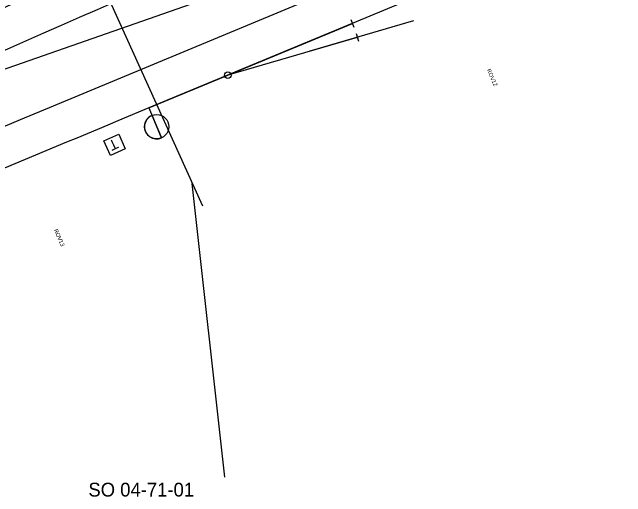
# Model space of a CAD drawing. Extents: x -723225 to -722352, y -1040354 to -1039760.
# Drawn here: x -723166.4 to -723090.8, y -1040339.7 to -1040280 of the extents above; entities that cross this region are included whole.
import ezdxf

# ---------------------------------------------------------------- set-up
doc = ezdxf.new("R2010")
doc.units = 0
for name, color, linetype in [('_PS_SO_číslo', 7, 'Continuous'), ('PS 05_01_01', 7, 'Continuous'), ('PS 05_02_22', 7, 'Continuous'), ('SO 03_01_01', 7, 'Continuous'), ('SO_04_71_01', 7, 'Continuous')]:
    doc.layers.add(name, color=color, linetype=linetype)

msp = doc.modelspace()

# ---------------------------------------------------------------- linework, layer by layer
at = {"layer": '_PS_SO_číslo'}
msp.add_line((-723140.168, -1040337.306), (-723144.203, -1040301.118), dxfattribs=at)
at = {"layer": 'PS 05_01_01'}
msp.add_lwpolyline([(-723219.2, -1040319.871), (-723217.435, -1040319.27), (-723221.975, -1040306.095), (-723205.95, -1040300.49), (-723139.101, -1040277.108), (-723140.23, -1040273.88), (-722952.74, -1040195.69), (-722956.655, -1040186.302)], dxfattribs=at)
at = {"layer": 'PS 05_02_22'}
msp.add_lwpolyline([(-723152.453, -1040296.855), (-723154.284, -1040297.661), (-723155.089, -1040295.83), (-723153.259, -1040295.025)], close=True, dxfattribs=at)
at = {"layer": 'SO 03_01_01'}
for p, q in [((-722770.304, -1040133.962), (-723149.54, -1040291.799)), ((-722866.065, -1040168.672), (-723161.343, -1040291.566)), ((-723116.934, -1040281.08), (-723129.722, -1040284.809)), ((-723124.677, -1040280.909), (-723124.293, -1040281.833)), ((-723124.014, -1040282.624), (-723123.734, -1040283.584))]:
    msp.add_line(p, q, dxfattribs=at)
for points in [[(-723123.874, -1040283.104), (-723139.825, -1040287.755), (-723149.54, -1040291.799), (-723139.825, -1040287.755), (-723124.485, -1040281.371)], [(-723161.343, -1040291.566), (-723165.382, -1040293.247), (-723169.421, -1040294.929), (-723173.459, -1040296.611), (-723177.497, -1040298.295), (-723181.534, -1040299.981), (-723185.57, -1040301.67), (-723189.605, -1040303.361), (-723193.639, -1040305.056), (-723197.67, -1040306.754), (-723199.213, -1040307.406)], [(-723149.54, -1040291.799), (-723148.003, -1040295.492)], [(-723148.003, -1040295.492), (-723149.156, -1040292.722)]]:
    msp.add_lwpolyline(points, dxfattribs=at)
for centre, radius in [((-723139.825, -1040287.755), 0.4), ((-723148.579, -1040294.107), 1.5)]:
    msp.add_circle(centre, radius, dxfattribs=at)
for centre, radius, start, end in [((-721755.577, -1043482.09), 3503, 112.596933, 114.444332), ((-721755.577, -1043482.09), 3500, 112.596933, 114.445987), ((-721753.55, -1043486.459), 3500, 113.186261, 114.449252), ((-719307.081, -1049524.107), 10000, 112.5969329, 112.8490239), ((-723148.579, -1040294.107), 1.5, 112.59693, 180), ((-723148.579, -1040294.107), 1.5, 180, 292.59693)]:
    msp.add_arc(centre, radius, start, end, dxfattribs=at)
at = {"layer": 'SO_04_71_01'}
msp.add_lwpolyline([(-723220.7, -1040260.497), (-723160.07, -1040266.004), (-723142.957, -1040303.876)], dxfattribs=at)

# ---------------------------------------------------------------- texts
at = {"layer": '_PS_SO_číslo'}
msp.add_text('SO 04-71-01', height=1.7, dxfattribs=at).set_placement((-723156.991, -1040339.686))
at = {"layer": 'PS 05_01_01'}
for s, p in [('ROV12', (-723107.941, -1040287.111)), ('ROV13', (-723161.261, -1040306.848))]:
    msp.add_text(s, height=0.5, rotation=293.93429, dxfattribs=at).set_placement(p)
at = {"layer": 'PS 05_02_22'}
msp.add_text('T', height=1.25, rotation=205.30908, dxfattribs=at).set_placement((-723153.711, -1040295.536))

doc.saveas('drawing.dxf')
